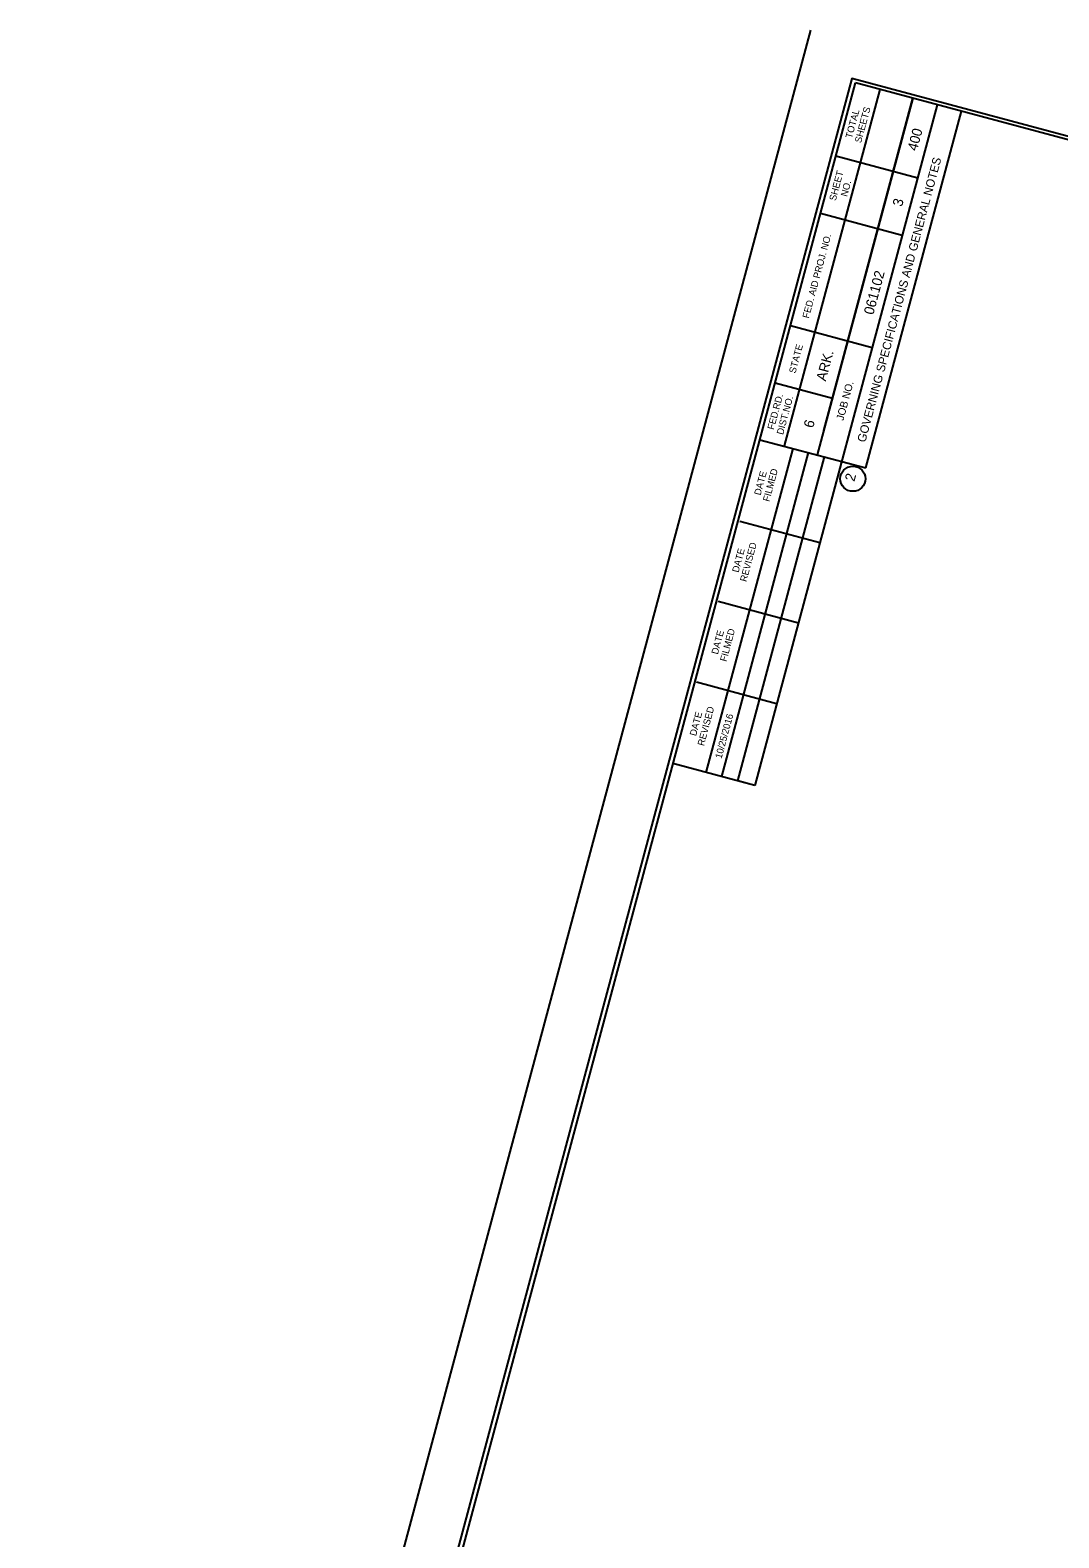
# Model space of a CAD drawing. Extents: x 1272249 to 1274802, y 195141 to 198564.
# Drawn here: x 1273273 to 1273878, y 197678 to 198564 of the extents above; entities that cross this region are included whole.
import ezdxf

# ---------------------------------------------------------------- set-up
doc = ezdxf.new("R2010")
doc.units = 0
doc.layers.add('R_Border', color=7, linetype='Continuous')
doc.layers.add('R_No Plot', color=7, linetype='Continuous')

msp = doc.modelspace()

# ---------------------------------------------------------------- linework, layer by layer
at = {"layer": 'R_Border'}
for p, q in [((1273731.93, 198564.4), (1273273.1, 196851.59)), ((1273346.17, 196994.88), (1273758.4, 198533.37)), ((1274758.15, 198265.52), (1273758.4, 198533.37)), ((1273772.79, 198529.46), (1273716.52, 198319.82)), ((1273792.17, 198524.32), (1273735.92, 198314.57)), ((1273739.78, 198328.97), (1273792.17, 198524.32)), ((1273772.61, 198529.56), (1273772.61, 198529.56)), ((1273806.48, 198520.49), (1273699.18, 198120.18)), ((1273764.44, 198306.93), (1273820.64, 198516.7)), ((1273746.82, 198490.53), (1273794.99, 198477.62)), ((1273737.81, 198456.7), (1273785.84, 198443.83)), ((1273720.17, 198390.65), (1273768.19, 198377.79)), ((1273711.13, 198356.93), (1273744.84, 198347.85)), ((1273670.65, 198127.78), (1273721.7, 198318.31)), ((1273702.13, 198323.52), (1273764.44, 198306.93)), ((1273679.72, 198125.4), (1273730.75, 198315.9)), ((1273689.11, 198122.88), (1273740.17, 198313.48)), ((1273737.39, 198262.8), (1273690.29, 198275.42)), ((1273724.81, 198215.64), (1273677.61, 198228.29)), ((1273712.02, 198168.11), (1273664.9, 198180.84)), ((1273699.18, 198120.18), (1273651.07, 198133.13)), ((1273699.18, 198120.18), (1273689.11, 198122.88))]:
    msp.add_line(p, q, dxfattribs=at)
msp.add_circle((1273756.85, 198300.53), 7.39, dxfattribs=at)
at = {"layer": 'R_No Plot'}
msp.add_lwpolyline([(1274347.9, 196724.34), (1274761.15, 198266.78), (1273756.3, 198536.04), (1273343.08, 196993.49)], close=True, dxfattribs=at)

# ---------------------------------------------------------------- texts
at = {"layer": 'R_Border'}
for s, height, rotation, p in [('TOTAL', 4.03, 75.00175, (1273756.3, 198500.44)), ('SHEETS', 4.03, 75.00175, (1273761.7, 198497.79)), ('400', 5.894, 75.00181, (1273794.5, 198493.01)), ('GOVERNING SPECIFICATIONS AND GENERAL NOTES', 5, 75.00181, (1273764.14, 198321.6)), ('SHEET', 4.03, 75.00175, (1273746.72, 198463.71)), ('NO.', 4.03, 75.00175, (1273753.48, 198466.17)), ('3', 5.89, 75.00181, (1273785.72, 198460.25)), ('FED. AID PROJ. NO.', 4.03, 75.00175, (1273730.96, 198394.58)), ('061102', 5.894, 75.00181, (1273768.84, 198396.63)), ('STATE', 4.03, 75.00175, (1273723.09, 198362.27)), ('ARK.', 5.905, 75.00175, (1273740.87, 198357.57)), ('JOB NO.', 4.429, 75.00175, (1273751.24, 198334.45)), ('FED.RD.', 4.03, 75.00175, (1273710.34, 198329.09)), ('DIST.NO.', 4.03, 75.00175, (1273715.81, 198326.13)), ('6', 5.91, 75.00175, (1273733.45, 198330.04)), ('DATE', 4.03, 75.00175, (1273702.57, 198290.53)), ('FILMED', 4.03, 75.00175, (1273707.72, 198286.78)), ('2', 5.91, 75.00175, (1273757.71, 198298.56)), ('DATE', 4.03, 75.00175, (1273689.62, 198245.08)), ('REVISED', 4.03, 75.00175, (1273694.26, 198239.63)), ('DATE', 4.03, 75.00175, (1273677.44, 198196.93)), ('FILMED', 4.03, 75.00175, (1273682.51, 198192.68)), ('REVISED', 4.03, 75.00175, (1273669.28, 198143.12)), ('DATE', 4.03, 75.00175, (1273664.63, 198148.94)), ('10/25/2016', 4.03, 75.00175, (1273679.62, 198135.62))]:
    msp.add_text(s, height=height, rotation=rotation, dxfattribs=at).set_placement(p)

doc.saveas('drawing.dxf')
